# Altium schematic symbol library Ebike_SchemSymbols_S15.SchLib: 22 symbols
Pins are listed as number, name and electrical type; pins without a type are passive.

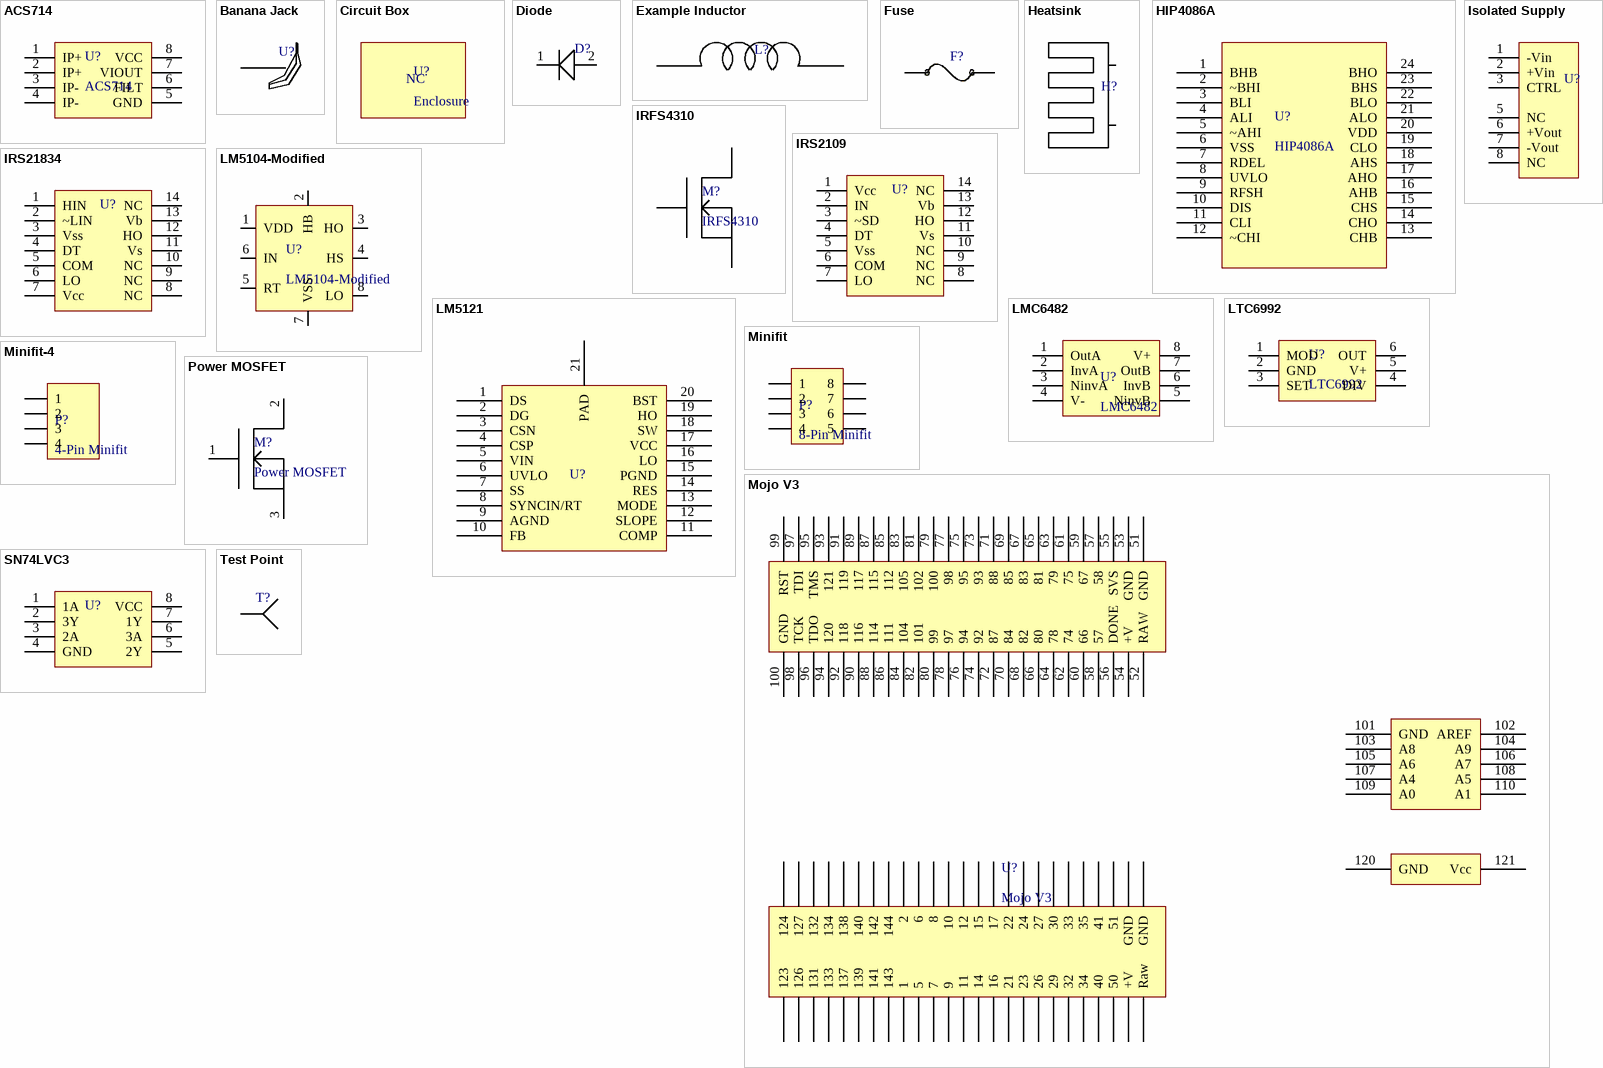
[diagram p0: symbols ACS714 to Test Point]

## ACS714
designator U?
Hall Effect Sensor IC
footprint SOIC-8 (ACS714 Hall Sensor)
pins: 1 IP+, 2 IP+, 3 IP-, 4 IP-, 5 GND, 6 FILT, 7 VIOUT, 8 VCC

## Banana Jack
designator U?  (value not drawn)
575-8
footprint Banana Jack (575-8)
pins: 1

## Circuit Box
designator U?, comment Enclosure
footprint Circuit Box (Ebike mounted circuit box)

## Diode
designator D?  (value not drawn)
Multiple
footprint TO220-2
footprint Axial
pins: 1, 2

## Example Inductor
designator L?  (value not drawn)
footprint Example Inductor (Coilcraft-FA2890-AL)
pins: 1, 2

## Fuse
designator F?  (value not drawn)
ATO/ATC .752" Fuse
footprint Fuse Holder (BK/1A1120-09-R  with  BK/ABC-30-R)
pins: 1, 2

## Heatsink
designator H?  (value not drawn)
530002B02500G
footprint Heatsink (Aavid 530002B02500G)
pins: 1, 2

## HIP4086A
designator U?
3-Phase Motor Driver
footprint DIP-24
footprint SOIC-24 (M24.3) (HIP4086 3-Phase Motor Drive SMD)
pins: 1 BHB, 2 ~BHI, 3 BLI, 4 ALI, 5 ~AHI, 6 VSS, 7 RDEL, 8 UVLO, 9 RFSH, 10 DIS, 11 CLI, 12 ~CHI, 13 CHB, 14 CHO, 15 CHS, 16 AHB, 17 AHO, 18 AHS, 19 CLO, 20 VDD, 21 ALO, 22 BLO, 23 BHS, 24 BHO

## IRFS4310
designator M?
100V, 120 A, 4.8 mOhm MOSFET
footprint IRFS4310 (D2-PAK, 3-Pads, Body 9.6x10.7mm (max), IPC Medium Density)
pins: 1 Gate, 3 Source, 4 Drain

## IRS2109
designator U?  (value not drawn)
Half-Bridge Driver
footprint DIP-14
pins: 1 Vcc, 2 IN, 3 ~SD, 4 DT, 5 Vss, 6 COM, 7 LO, 8 NC, 9 NC, 10 NC, 11 Vs, 12 HO, 13 Vb, 14 NC

## IRS21834
designator U?  (value not drawn)
Half-Bridge Driver
footprint DIP-14
pins: 1 HIN, 2 ~LIN, 3 Vss, 4 DT, 5 COM, 6 LO, 7 Vcc, 8 NC, 9 NC, 10 NC, 11 Vs, 12 HO, 13 Vb, 14 NC

## Isolated Supply
designator U?, comment Iso Supply  (value not drawn)
RSO-24xxS
footprint RSO-24xxS (Isolated 18-36Vin, 2W, xxVout)
pins: 1 -Vin, 2 +Vin, 3 CTRL, 5 NC, 6 +Vout, 7 -Vout, 8 NC

## LM5104-Modified
designator U?
Half-Bridge Driver
footprint Half Bridge Driver (LM5104, 8-SOIC)
pins: 1 VDD, 2 HB, 3 HO, 4 HS, 5 RT, 6 IN, 7 VSS, 8 LO

## LM5121
designator U?  (value not drawn)
V/I Boost Controller With Disconnect
footprint LM5121 (PWP0020A, 20 pin HTSSOP with thermal pad)
pins: 1 DS, 2 DG, 3 CSN, 4 CSP, 5 VIN, 6 UVLO, 7 SS, 8 SYNCIN/RT, 9 AGND, 10 FB, 11 COMP, 12 SLOPE, 13 MODE, 14 RES, 15 PGND, 16 LO, 17 VCC, 18 SW, 19 HO, 20 BST, 21 PAD

## LMC6482
designator U?
Dual Op-Amp Rail-to-Rail
footprint DIP-8 (DIP; 8 Leads; Row Spacing 7.62 mm; Pitch 2.54 mm)
pins: 1 OutA, 2 InvA, 3 NinvA, 4 V-, 5 NinvB, 6 InvB, 7 OutB, 8 V+

## LTC6992
designator U?
Voltage Controller PWM
footprint TSOT-23 (S6) (LTC6992, TSOT-23 package)
pins: 1 MOD, 2 GND, 3 SET, 4 DIV, 5 V+, 6 OUT

## Minifit
designator P?, comment 8-Pin Minifit
538-43045-0812   board connector straight
footprint 8-pin minifit (538-43045-0812   board connector straight)
pins: 1, 2, 3, 4, 5, 6, 7, 8

## Minifit-4
designator P?, comment 4-Pin Minifit
538-43045-0412  board connector straight
footprint 4-pin minifit (538-43045-0412   board connector straight)
pins: 1, 2, 3, 4

## Mojo V3
designator U?
FPGA + uP Dev Board
footprint Mojo V3
pins: 1 GND, 2 Raw, 3 GND, 4 +V, 5 51, 6 50, 7 41, 8 40, 9 35, 10 34, 11 33, 12 32, 13 30, 14 29, 15 27, 16 26, 17 24, 18 23, 19 22, 20 21, 21 17, 22 16, 23 15, 24 14, 25 12, 26 11, 27 10, 28 9, 29 8, 30 7, 31 6, 32 5, 33 2, 34 1, 35 144, 36 143, 37 142, 38 141, 39 140, 40 139, 41 138, 42 137, 43 134, 44 133, 45 132, 46 131, 47 127, 48 126, 49 124, 50 123, 51 GND, 52 RAW, 53 GND, 54 +V, 55 SVS, 56 DONE, 57 58, 58 57, 59 67, 60 66, 61 75, 62 74, 63 79, 64 78, 65 81, 66 80, 67 83, 68 82, 69 85, 70 84, 71 88, 72 87, 73 93, 74 92, 75 95, 76 94, 77 98, 78 97, 79 100, 80 99, 81 102, 82 101, 83 105, 84 104, 85 112, 86 111, 87 115, 88 114, 89 117, 90 116, 91 119, 92 118, 93 121, 94 120, 95 TMS, 96 TDO, 97 TDI, 98 TCK, 99 RST, 100 GND, 101 GND, 102 AREF, 103 A8, 104 A9, 105 A6, 106 A7, 107 A4, 108 A5, 109 A0, 110 A1, 120 GND, 121 Vcc

## Power MOSFET
designator M?
Multiple
footprint TO220-3
pins: 1 Gate, 2 Drain, 3 Source

## SN74LVC3
designator U?, comment Triple Schmitt Trigger  (value not drawn)
SN74LVC3G17DCTR
pins: 1 1A, 2 3Y, 3 2A, 4 GND, 5 2Y, 6 3A, 7 1Y, 8 VCC

## Test Point
designator T?, comment Net  (value not drawn)
Keystone 500(0-4) Series
footprint Test Point (Keystone 500(0-4))
pins: 1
